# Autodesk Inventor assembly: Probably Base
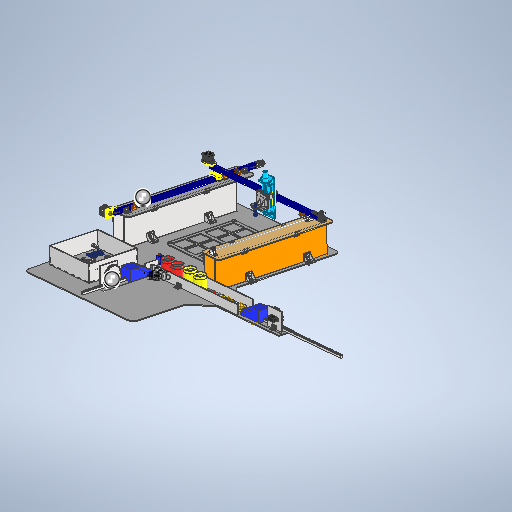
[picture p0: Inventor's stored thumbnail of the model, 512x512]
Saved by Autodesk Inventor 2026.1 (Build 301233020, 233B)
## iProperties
Created: 2026-10
Part Number: Probably Base
Document SubType Name: Assembly
Designer: hp
Author: hp
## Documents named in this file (64)
- C:\Users\hp\Documents\Inventor\DOM1_CartesianRobot\Probably Base.iam
- C:\Users\hp\Documents\Inventor\DOM1_CartesianRobot\StorageArea.ipt
- C:\Users\hp\Documents\Inventor\DOM1_CartesianRobot\BigBase.ipt
- C:\Users\hp\Documents\Inventor\DOM1_CartesianRobot\Side Wall Support.ipt
- C:\Users\hp\Documents\Inventor\DOM1_CartesianRobot\Belt Support.ipt
- C:\Users\hp\Documents\Inventor\DOM1_CartesianRobot\Assieme_guida_2020_nema.iam
- C:\Users\hp\Documents\Inventor\DOM1_CartesianRobot\Assieme_guida_2020_nema - Copy.iam
- C:\Users\hp\Documents\Inventor\DOM1_CartesianRobot\aluminum rod.ipt
- C:\Users\hp\Documents\Inventor\DOM1_CartesianRobot\color_sensor_holder.iam
- C:\Users\hp\Documents\Inventor\DOM1_CartesianRobot\IR_LM393_pin.ipt
- C:\Users\hp\Documents\Inventor\DOM1_CartesianRobot\reciever_wall.ipt
- C:\Users\hp\Documents\Inventor\DOM1_CartesianRobot\laser_assembly.iam
- C:\Users\hp\Documents\Inventor\DOM1_CartesianRobot\laser_detector.iam
- C:\Users\hp\Documents\Inventor\DOM1_CartesianRobot\pusher.iam
- C:\Users\hp\Documents\Inventor\DOM1_CartesianRobot\piatto.ipt
- C:\Users\hp\Documents\Inventor\DOM1_CartesianRobot\z axis screw.iam
- C:\Users\hp\Documents\Inventor\DOM1_CartesianRobot\z_Bearing_Housing_Assembly.iam
- C:\Users\hp\Documents\Inventor\DOM1_CartesianRobot\tool_mout_assembly.iam
- C:\Users\hp\Documents\Inventor\DOM1_CartesianRobot\Side Wall Support 2.ipt
- C:\Users\hp\Documents\Inventor\DOM1_CartesianRobot\filler.ipt
- C:\Users\hp\Documents\Inventor\DOM1_CartesianRobot\L-Bracket.ipt
- C:\Users\hp\Documents\Inventor\DOM1_CartesianRobot\Belt Support_v2.ipt
- C:\Users\hp\Documents\Inventor\DOM1_CartesianRobot\8mm_Railclamp.ipt
- C:\Users\hp\Documents\Inventor\DOM1_CartesianRobot\SC8UU Linear Rail Bearing v5.ipt
- C:\Users\hp\Documents\Inventor\Content Center Files\R2026\en-US\ISO 4017(1)\ISO 4017 - M10 x 25 - ISO.ipt
- C:\Users\hp\Documents\Inventor\Content Center Files\R2026\en-US\ISO 7041\ISO 7041 - M10 - ISO.ipt
- C:\Users\hp\Documents\Inventor\Content Center Files\R2026\en-US\ISO 4762(2)\ISO 4762 - M5 x 20ISO.ipt
- C:\Users\hp\Documents\Inventor\Content Center Files\R2026\en-US\ISO 7041\ISO 7041 - M5 - ISO.ipt
- C:\Users\hp\Documents\Inventor\DOM1_CartesianRobot\4040 Corner Bracket Right Angle L Shape.ipt
- C:\Users\hp\Documents\Inventor\Content Center Files\R2026\en-US\ISO 4762(2)\ISO 4762 - M6 x 20ISO.ipt
- C:\Users\hp\Documents\Inventor\Content Center Files\R2026\en-US\ISO 7041\ISO 7041 - M6 - ISO.ipt
- C:\Users\hp\Documents\Inventor\Content Center Files\R2026\en-US\JIS B 1111(2)\JIS B 1111 - M3x40(2).ipt
- C:\Users\hp\Documents\Inventor\DOM1_CartesianRobot\2020 M3.ipt
- C:\Users\hp\Documents\Inventor\Content Center Files\R2026\en-US\ISO 4017(1)\ISO 4017 - M4 x 35 - ISO.ipt
- C:\Users\hp\Documents\Inventor\DOM1_CartesianRobot\2020 M4 (1).ipt
- C:\Users\hp\Documents\Inventor\Content Center Files\R2026\en-US\ISO 4017(1)\ISO 4017 - M4 x 30 - ISO.ipt
- C:\Users\hp\Documents\Inventor\Content Center Files\R2026\en-US\ISO 4032(2)\ISO 4032 - M4 - ISO.ipt
- C:\Users\hp\Documents\Inventor\Content Center Files\R2026\en-US\ISO 4017(1)\ISO 4017 - M4 x 12 - ISO.ipt
- C:\Users\hp\Documents\Inventor\DOM1_CartesianRobot\feeder.iam
- C:\Users\hp\Documents\Inventor\DOM1_CartesianRobot\red_base.ipt
- C:\Users\hp\Documents\Inventor\DOM1_CartesianRobot\Feeder Side Wall.ipt
- C:\Users\hp\Documents\Inventor\Content Center Files\R2026\en-US\ISO 4017(1)\ISO 4017 - M4 x 8 - ISO.ipt
- C:\Users\hp\Documents\Inventor\Content Center Files\R2026\en-US\ISO 4017(1)\ISO 4017 - M5 x 20 - ISO.ipt
- C:\Users\hp\Documents\Inventor\Content Center Files\R2026\en-US\ISO 4032(2)\ISO 4032 - M5 - ISO.ipt
- C:\Users\hp\Documents\Inventor\DOM1_CartesianRobot\Side Wall Support_v1_B.ipt
- C:\Users\hp\Documents\Inventor\DOM1_CartesianRobot\Side Wall Support 2 (B).ipt
- C:\Users\hp\Documents\Inventor\Content Center Files\R2026\en-US\ISO 4017(1)\ISO 4017 - M8 x 25 - ISO.ipt
- C:\Users\hp\Documents\Inventor\Content Center Files\R2026\en-US\ISO 4032(2)\ISO 4032 - M8 - ISO.ipt
- C:\Users\hp\Documents\Inventor\Content Center Files\R2026\en-US\ISO 4017(1)\ISO 4017 - M8 x 16 - ISO.ipt
- C:\Users\hp\Documents\Inventor\Content Center Files\R2026\en-US\ISO 4017(1)\ISO 4017 - M8 x 20 - ISO.ipt
- C:\Users\hp\Documents\Inventor\Content Center Files\R2026\en-US\ISO 4035(2)\ISO 4035 - M4 - ISO.ipt
- C:\Users\hp\Documents\Inventor\DOM1_CartesianRobot\yellow_base.ipt
- C:\Users\hp\Documents\Inventor\DOM1_CartesianRobot\red_lid.ipt
- C:\Users\hp\Documents\Inventor\DOM1_CartesianRobot\yellow_lid.ipt
- C:\Users\hp\Documents\Inventor\DOM1_CartesianRobot\Color Sensor holder.ipt
- C:\Users\hp\Documents\Inventor\DOM1_CartesianRobot\color_sensor_holder_top.ipt
- C:\Users\hp\Documents\Inventor\Content Center Files\R2026\en-US\ISO 7045  H\ISO 7045 - M3 x 16_ - 4.8 - H - ISO.ipt
- C:\Users\hp\Documents\Inventor\Content Center Files\R2026\en-US\ISO 4032(2)\ISO 4032 - M3 - ISO.ipt
- C:\Users\hp\Documents\Inventor\Content Center Files\R2026\en-US\ISO 4014(2)\ISO 4014 - M5 x 25 - ISO.ipt
- C:\Users\hp\Documents\Inventor\DOM1_CartesianRobot\Control Box.iam
- C:\Users\hp\Documents\Inventor\DOM1_CartesianRobot\ESP-32.ipt
- C:\Users\hp\Documents\Inventor\DOM1_CartesianRobot\DRV8825_pin_heatsink.ipt
- C:\Users\hp\Documents\Inventor\DOM1_CartesianRobot\L298N Motor Driver.iam
- C:\Users\hp\Documents\Inventor\DOM1_CartesianRobot\Buck_XY3606.ipt
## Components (282 placed, 63 different names)
1. StorageArea:1
2. BigBase:1
3. Assieme_guida_2020_nema:1 [sub-assembly]
4. Side Wall Support:1
5. Side Wall Support_v1_B:1
6. Belt Support:1
7. Belt Support_v2:1
8. Assieme_guida_2020_nema - Copy:1 [sub-assembly]
9. color_sensor_holder:1 [sub-assembly] — Mate:649, Mate:650, Flush:61
10. IR_LM393_pin:1 — Mate:36, Mate:339, Mate:654
11. reciever_wall:1 — Mate:34, Flush:17, Mate:35, Flush:19
12. laser_assembly:1 [sub-assembly] — Mate:40, Mate:343
13. laser_detector:1 [sub-assembly] — Flush:19, Mate:41
14. piatto:1
15. piatto:2 — Mate:48, Slider:2, Mate:71, Mate:72, Mate:117, Mate:161
16. z_Bearing_Housing_Assembly:1 [sub-assembly]
17. tool_mout_assembly:1 [sub-assembly]
18. Side Wall Support 2:1
19. Side Wall Support 2 (B):1
20. filler:1 — Mate:79, Flush:30, Flush:31, Flush:33, Mate:170, Mate:172
21. L-Bracket:1
22. L-Bracket:2 — Mate:83, Mate:84, Mate:90, Mate:234, Mate:236, Mate:250, Mate:252
23. L-Bracket:3
24. L-Bracket:4
25. 8mm_Railclamp:1
26. 8mm_Railclamp:2 — Mate:92, Mate:93, Flush:37, Mate:434, Mate:436, Mate:442, Mate:444
27. aluminum rod:1 — Mate:94, Flush:38, Mate:95
28. SC8UU Linear Rail Bearing v5:1 — Mate:95, Angle:1, Flush:39, Mate:162, Mate:163, Mate:164, Mate:165
29. ISO 4017 M10 x 25:1 — Mate:96, Mate:97
30. ISO 7041 M10:1 — Mate:104, Mate:105
31. ISO 4017 M10 x 25:2 — Mate:98, Mate:99
32. ISO 4017 M10 x 25:3 — Mate:100, Mate:101
33. ISO 4017 M10 x 25:4 — Mate:102, Mate:103
34. ISO 7041 M10:2 — Mate:106, Mate:107
35. ISO 7041 M10:3 — Mate:108, Mate:109
36. ISO 7041 M10:4 — Mate:110, Mate:111
37. ISO 4762 M5 x 20:1 — Mate:114, Mate:115
38. ISO 7041 M5:1 — Mate:116, Mate:117
39. 4040 Corner Bracket Right Angle L Shape:1
40. 4040 Corner Bracket Right Angle L Shape:2
41. 4040 Corner Bracket Right Angle L Shape:3
42. 4040 Corner Bracket Right Angle L Shape:4 — Mate:124, Mate:125, Mate:127, Mate:478, Mate:510
43. 4040 Corner Bracket Right Angle L Shape:5 — Mate:135, Mate:137, Mate:480, Mate:512
44. 4040 Corner Bracket Right Angle L Shape:6 — Mate:134, Mate:136, Mate:179, Mate:464, Mate:488, Mate:520
45. 4040 Corner Bracket Right Angle L Shape:7 — Mate:130, Mate:133, Mate:484, Mate:516
46. 4040 Corner Bracket Right Angle L Shape:8
47. 4040 Corner Bracket Right Angle L Shape:9
48. 4040 Corner Bracket Right Angle L Shape:10
49. 4040 Corner Bracket Right Angle L Shape:11 — Mate:144, Mate:145, Mate:504, Mate:536
50. 4040 Corner Bracket Right Angle L Shape:12
51. 4040 Corner Bracket Right Angle L Shape:13
52. 4040 Corner Bracket Right Angle L Shape:14 — Mate:156, Mate:157, Mate:496, Mate:528
53. 4040 Corner Bracket Right Angle L Shape:15
54. 4040 Corner Bracket Right Angle L Shape:16 — Mate:151, Mate:152, Mate:459, Mate:461, Mate:492, Mate:524
55. ISO 4762 M6 x 20:1 — Mate:158, Mate:159
56. ISO 7041 M6:1 — Mate:160, Mate:161
57. JIS B 1111 M3x40:1 — Mate:162, Mate:163, Mate:168
58. JIS B 1111 M3x40:2 — Mate:164, Mate:165, Mate:169
59. 2020 M3:1 — Mate:166, Angle:2, Mate:168
60. 2020 M3:2 — Mate:167, Angle:3, Mate:169
61. ISO 4017 M4 x 35:1 — Mate:170, Mate:171, Mate:176
62. ISO 4017 M4 x 35:2 — Mate:172, Mate:173, Mate:177
63. 2020 M4 (1):1 — Mate:174, Angle:4, Mate:176
64. 2020 M4 (1):2 — Mate:175, Angle:5, Mate:177
65. L-Bracket:5
66. L-Bracket:6
67. L-Bracket:7
68. L-Bracket:8
69. L-Bracket:9
70. L-Bracket:10
71. L-Bracket:11
72. L-Bracket:12
73. ISO 4017 M4 x 30:1 — Mate:208, Mate:209
74. ISO 4032 M4:1 — Mate:216, Mate:217
75. ISO 4017 M4 x 30:2 — Mate:210, Mate:211
76. ISO 4017 M4 x 30:3 — Mate:212, Mate:213
77. ISO 4017 M4 x 30:4 — Mate:214, Mate:215
78. ISO 4032 M4:2 — Mate:218, Mate:219
79. ISO 4032 M4:3 — Mate:220, Mate:221
80. ISO 4032 M4:4 — Mate:222, Mate:223
81. ISO 4017 M4 x 12:1 — Mate:224, Mate:225
82. ISO 4032 M4:5 — Mate:240, Mate:241
83. ISO 4017 M4 x 12:2 — Mate:226, Mate:227
84. ISO 4017 M4 x 12:3 — Mate:228, Mate:229
85. ISO 4017 M4 x 12:4 — Mate:230, Mate:231
86. ISO 4017 M4 x 12:5 — Mate:232, Mate:233
87. ISO 4017 M4 x 12:6 — Mate:234, Mate:235
88. ISO 4017 M4 x 12:7 — Mate:236, Mate:237
89. ISO 4017 M4 x 12:8 — Mate:238, Mate:239
90. ISO 4032 M4:6 — Mate:242, Mate:243
91. ISO 4032 M4:7 — Mate:244, Mate:245
92. ISO 4032 M4:8 — Mate:246, Mate:247
93. ISO 4032 M4:9 — Mate:248, Mate:249
94. ISO 4032 M4:10 — Mate:250, Mate:251
95. ISO 4032 M4:11 — Mate:252, Mate:253
96. ISO 4032 M4:12 — Mate:254, Mate:255
97. ISO 4017 M4 x 12:9 — Mate:305, Mate:306
98. ISO 4032 M4:13 — Mate:321, Mate:322
99. ISO 4017 M4 x 12:10 — Mate:307, Mate:308
100. ISO 4017 M4 x 12:11 — Mate:309, Mate:310
101. ISO 4017 M4 x 12:12 — Mate:311, Mate:312
102. ISO 4017 M4 x 12:13 — Mate:313, Mate:314
103. ISO 4017 M4 x 12:14 — Mate:315, Mate:316
104. ISO 4017 M4 x 12:15 — Mate:317, Mate:318
105. ISO 4017 M4 x 12:16 — Mate:319, Mate:320
106. ISO 4032 M4:14 — Mate:323, Mate:324
107. ISO 4032 M4:15 — Mate:325, Mate:326
108. ISO 4032 M4:16 — Mate:327, Mate:328
109. ISO 4032 M4:17 — Mate:329, Mate:330
110. ISO 4032 M4:18 — Mate:331, Mate:332
111. ISO 4032 M4:19 — Mate:333, Mate:334
112. ISO 4032 M4:20 — Mate:335, Mate:336
113. feeder:1 [sub-assembly] — Flush:56, Flush:57, Flush:58, Mate:629, Mate:630, Mate:636, Mate:638
114. pusher:1 [sub-assembly] — Flush:45, Mate:337, Flush:48, Mate:611, Flush:59, Mate:617, Mate:619
115. red_base:1 — Mate:340
116. Feeder Side Wall:1 — Mate:361, Flush:54, Flush:55
117. Feeder Side Wall:2 — Mate:342, Flush:51, Flush:52, Mate:343, Mate:347
118. L-Bracket:13
119. L-Bracket:14
120. ISO 4017 M4 x 8:1 — Mate:357, Mate:358
121. ISO 4017 M4 x 8:2 — Mate:359, Mate:360
122. ISO 4017 M4 x 8:3 — Mate:362, Mate:363
123. ISO 4017 M4 x 8:4 — Mate:364, Mate:365
124. ISO 4017 M4 x 12:17 — Mate:366, Mate:367
125. ISO 4032 M4:21 — Mate:374, Mate:375
126. ISO 4017 M4 x 12:18 — Mate:368, Mate:369
127. ISO 4017 M4 x 12:19 — Mate:370, Mate:371
128. ISO 4017 M4 x 12:20 — Mate:372, Mate:373
129. ISO 4032 M4:22 — Mate:376, Mate:377
130. ISO 4032 M4:23 — Mate:378, Mate:379
131. ISO 4032 M4:24 — Mate:380, Mate:381
132. ISO 4017 M4 x 12:21 — Mate:382, Mate:383
133. ISO 4032 M4:25 — Mate:390, Mate:391
134. ISO 4017 M4 x 12:22 — Mate:384, Mate:385
135. ISO 4017 M4 x 12:23 — Mate:386, Mate:387
136. ISO 4017 M4 x 12:24 — Mate:388, Mate:389
137. ISO 4032 M4:26 — Mate:392, Mate:393
138. ISO 4032 M4:27 — Mate:394, Mate:395
139. ISO 4032 M4:28 — Mate:396, Mate:397
140. ISO 4017 M4 x 12:25 — Mate:398, Mate:399
141. ISO 4032 M4:29 — Mate:406, Mate:407
142. ISO 4017 M4 x 12:26 — Mate:400, Mate:401
143. ISO 4017 M4 x 12:27 — Mate:402, Mate:403
144. ISO 4017 M4 x 12:28 — Mate:404, Mate:405
145. ISO 4032 M4:30 — Mate:408, Mate:409
146. ISO 4032 M4:31 — Mate:410, Mate:411
147. ISO 4032 M4:32 — Mate:412, Mate:413
148. ISO 4017 M4 x 12:29 — Mate:414, Mate:415
149. ISO 4032 M4:33 — Mate:422, Mate:423
150. ISO 4017 M4 x 12:30 — Mate:416, Mate:417
151. ISO 4017 M4 x 12:31 — Mate:418, Mate:419
152. ISO 4017 M4 x 12:32 — Mate:420, Mate:421
153. ISO 4032 M4:34 — Mate:424, Mate:425
154. ISO 4032 M4:35 — Mate:426, Mate:427
155. ISO 4032 M4:36 — Mate:428, Mate:429
156. ISO 4017 M5 x 20:1 — Mate:430, Mate:431
157. ISO 4032 M5:1 — Mate:438, Mate:439
158. ISO 4017 M5 x 20:2 — Mate:432, Mate:433
159. ISO 4017 M5 x 20:3 — Mate:434, Mate:435
160. ISO 4017 M5 x 20:4 — Mate:436, Mate:437
161. ISO 4032 M5:2 — Mate:440, Mate:441
162. ISO 4032 M5:3 — Mate:442, Mate:443
163. ISO 4032 M5:4 — Mate:444, Mate:445
164. ISO 4017 M8 x 25:1 — Mate:446, Mate:447
165. ISO 4032 M8:1 — Mate:450, Mate:451
166. ISO 4017 M8 x 25:2 — Mate:448, Mate:449
167. ISO 4032 M8:2 — Mate:452, Mate:453
168. ISO 4017 M8 x 25:3 — Mate:454, Mate:455
169. ISO 4032 M8:3 — Mate:458, Mate:459
170. ISO 4017 M8 x 25:4 — Mate:456, Mate:457
171. ISO 4032 M8:4 — Mate:460, Mate:461
172. ISO 4017 M8 x 16:1 — Mate:462, Mate:463
173. ISO 4017 M8 x 16:2 — Mate:464, Mate:465
174. ISO 4017 M8 x 25:5 — Mate:466, Mate:467
175. ISO 4032 M8:5 — Mate:470, Mate:471
176. ISO 4017 M8 x 25:6 — Mate:468, Mate:469
177. ISO 4032 M8:6 — Mate:472, Mate:473
178. ISO 4017 M8 x 20:1 — Mate:474, Mate:475
179. ISO 4032 M8:7 — Mate:506, Mate:507
180. ISO 4017 M8 x 20:2 — Mate:476, Mate:477
181. ISO 4017 M8 x 20:3 — Mate:478, Mate:479
182. ISO 4017 M8 x 20:4 — Mate:480, Mate:481
183. ISO 4017 M8 x 20:5 — Mate:482, Mate:483
184. ISO 4017 M8 x 20:6 — Mate:484, Mate:485
185. ISO 4017 M8 x 20:7 — Mate:486, Mate:487
186. ISO 4017 M8 x 20:8 — Mate:488, Mate:489
187. ISO 4017 M8 x 20:9 — Mate:490, Mate:491
188. ISO 4017 M8 x 20:10 — Mate:492, Mate:493
189. ISO 4017 M8 x 20:11 — Mate:494, Mate:495
190. ISO 4017 M8 x 20:12 — Mate:496, Mate:497
191. ISO 4017 M8 x 20:13 — Mate:498, Mate:499
192. ISO 4017 M8 x 20:14 — Mate:500, Mate:501
193. ISO 4017 M8 x 20:15 — Mate:502, Mate:503
194. ISO 4017 M8 x 20:16 — Mate:504, Mate:505
195. ISO 4032 M8:8 — Mate:508, Mate:509
196. ISO 4032 M8:9 — Mate:510, Mate:511
197. ISO 4032 M8:10 — Mate:512, Mate:513
198. ISO 4032 M8:11 — Mate:514, Mate:515
199. ISO 4032 M8:12 — Mate:516, Mate:517
200. ISO 4032 M8:13 — Mate:518, Mate:519
201. ISO 4032 M8:14 — Mate:520, Mate:521
202. ISO 4032 M8:15 — Mate:522, Mate:523
203. ISO 4032 M8:16 — Mate:524, Mate:525
204. ISO 4032 M8:17 — Mate:526, Mate:527
205. ISO 4032 M8:18 — Mate:528, Mate:529
206. ISO 4032 M8:19 — Mate:530, Mate:531
207. ISO 4032 M8:20 — Mate:532, Mate:533
208. ISO 4032 M8:21 — Mate:534, Mate:535
209. ISO 4032 M8:22 — Mate:536, Mate:537
210. ISO 4017 M4 x 35:3 — Mate:538, Mate:539
211. ISO 4035 M4:1 — Mate:546, Mate:547
212. ISO 4017 M4 x 35:4 — Mate:540, Mate:541
213. ISO 4017 M4 x 35:5 — Mate:542, Mate:543
214. ISO 4017 M4 x 35:6 — Mate:544, Mate:545
215. ISO 4035 M4:2 — Mate:548, Mate:549
216. ISO 4035 M4:3 — Mate:550, Mate:551
217. ISO 4035 M4:4 — Mate:552, Mate:553
218. ISO 4017 M4 x 12:33 — Mate:554, Mate:555
219. ISO 4032 M4:37 — Mate:570, Mate:571
220. ISO 4017 M4 x 12:34 — Mate:556, Mate:557
221. ISO 4017 M4 x 12:35 — Mate:558, Mate:559
222. ISO 4017 M4 x 12:36 — Mate:560, Mate:561
223. ISO 4017 M4 x 12:37 — Mate:562, Mate:563
224. ISO 4017 M4 x 12:38 — Mate:564, Mate:565
225. ISO 4017 M4 x 12:39 — Mate:566, Mate:567
226. ISO 4017 M4 x 12:40 — Mate:568, Mate:569
227. ISO 4032 M4:38 — Mate:572, Mate:573
228. ISO 4032 M4:39 — Mate:574, Mate:575
229. ISO 4032 M4:40 — Mate:576, Mate:577
230. ISO 4032 M4:41 — Mate:578, Mate:579
231. ISO 4032 M4:42 — Mate:580, Mate:581
232. ISO 4032 M4:43 — Mate:582, Mate:583
233. ISO 4032 M4:44 — Mate:584, Mate:585
234. red_base:2 — Mate:586
235. yellow_base:1 — Mate:587
236. yellow_base:2 — Mate:588
237. red_lid:1 — Mate:589
238. red_lid:2 — Mate:591
239. yellow_lid:1 — Mate:590
240. yellow_lid:2 — Mate:592
241. ISO 4017 M4 x 12:41 — Mate:594, Mate:595
242. ISO 4032 M4:45 — Mate:602, Mate:603
243. ISO 4017 M4 x 12:42 — Mate:596, Mate:597
244. ISO 4017 M4 x 12:43 — Mate:598, Mate:599
245. ISO 4017 M4 x 12:44 — Mate:600, Mate:601
246. ISO 4032 M4:46 — Mate:604, Mate:605
247. ISO 4032 M4:47 — Mate:606, Mate:607
248. ISO 4032 M4:48 — Mate:608, Mate:609
249. L-Bracket:15
250. ISO 4017 M4 x 12:45 — Mate:612, Mate:613
251. ISO 4032 M4:49 — Mate:616, Mate:617
252. ISO 4017 M4 x 12:46 — Mate:614, Mate:615
253. ISO 4032 M4:50 — Mate:618, Mate:619
254. ISO 4017 M4 x 12:47 — Mate:620, Mate:621
255. ISO 4032 M4:51 — Mate:624, Mate:625
256. ISO 4017 M4 x 12:48 — Mate:622, Mate:623
257. ISO 4032 M4:52 — Mate:626, Mate:627
258. L-Bracket:16
259. ISO 4017 M4 x 12:49 — Mate:631, Mate:632
260. ISO 4032 M4:53 — Mate:635, Mate:636
261. ISO 4017 M4 x 12:50 — Mate:633, Mate:634
262. ISO 4032 M4:54 — Mate:637, Mate:638
263. ISO 4017 M4 x 12:51 — Mate:639, Mate:640
264. ISO 4032 M4:55 — Mate:643, Mate:644
265. ISO 4017 M4 x 12:52 — Mate:641, Mate:642
266. ISO 4032 M4:56 — Mate:645, Mate:646
267. Color Sensor holder:1
268. color_sensor_holder_top:1 — Mate:651, Mate:652
269. ISO 7045 H M3 x 16 - 4.8 - H:1 — Mate:653, Mate:654
270. ISO 4032 M3:1 — Mate:655, Mate:656
271. ISO 4014 M5 x 25:1 — Mate:658, Mate:659
272. ISO 4032 M5:5 — Mate:662, Mate:663
273. ISO 4014 M5 x 25:2 — Mate:660, Mate:661
274. ISO 4032 M5:6 — Mate:664, Mate:665
275. Control Box:1 [sub-assembly] — Mate:666, Flush:62, Mate:667, Mate:668, Mate:669, Mate:670, Mate:671, Mate:672
276. ESP-32:1 — Mate:668
277. ESP-32:2 — Mate:667
278. DRV8825_pin_heatsink:1
279. DRV8825_pin_heatsink:2
280. L298N Motor Driver:1 [sub-assembly] — Mate:669
281. Buck_XY3606:1 — Mate:672
282. z axis screw:1 [sub-assembly]
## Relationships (494: Mate 468, Flush 20, Angle 5, TranslationJoint 1)
- Mate:34: reciever_wall:1
- Flush:17: reciever_wall:1
- Mate:35: reciever_wall:1
- Mate:36: IR_LM393_pin:1
- Mate:40: laser_assembly:1
- Flush:19: reciever_wall:1 ↔ laser_detector:1
- Mate:41: laser_detector:1
- Mate:48: piatto:2
- Slider:2 [TranslationJoint]: piatto:2
- Mate:71: piatto:2
- Mate:72: piatto:2
- Mate:79: filler:1
- Flush:30: filler:1
- Flush:31: filler:1
- Mate:83: L-Bracket:2
- Mate:84: L-Bracket:2
- Mate:90: L-Bracket:2
- Flush:33: filler:1
- Mate:92: 8mm_Railclamp:2
- Mate:93: 8mm_Railclamp:2
- Flush:37: 8mm_Railclamp:2
- Mate:94: aluminum rod:1
- Flush:38: aluminum rod:1
- Mate:95: aluminum rod:1 ↔ SC8UU Linear Rail Bearing v5:1
- Angle:1: SC8UU Linear Rail Bearing v5:1
- Mate:96: ISO 4017 M10 x 25:1
- Mate:97: ISO 4017 M10 x 25:1
- Mate:98: ISO 4017 M10 x 25:2
- Mate:99: ISO 4017 M10 x 25:2
- Mate:100: ISO 4017 M10 x 25:3
- Mate:101: ISO 4017 M10 x 25:3
- Mate:102: ISO 4017 M10 x 25:4
- Mate:103: ISO 4017 M10 x 25:4
- Mate:104: ISO 7041 M10:1
- Mate:105: ISO 7041 M10:1
- Mate:106: ISO 7041 M10:2
- Mate:107: ISO 7041 M10:2
- Mate:108: ISO 7041 M10:3
- Mate:109: ISO 7041 M10:3
- Mate:110: ISO 7041 M10:4
- Mate:111: ISO 7041 M10:4
- Mate:114: ISO 4762 M5 x 20:1
- Mate:115: ISO 4762 M5 x 20:1
- Mate:116: ISO 7041 M5:1
- Mate:117: piatto:2 ↔ ISO 7041 M5:1
- Mate:124: 4040 Corner Bracket Right Angle L Shape:4
- Mate:125: 4040 Corner Bracket Right Angle L Shape:4
- Mate:127: 4040 Corner Bracket Right Angle L Shape:4
- Mate:130: 4040 Corner Bracket Right Angle L Shape:7
- Mate:133: 4040 Corner Bracket Right Angle L Shape:7
- Mate:134: 4040 Corner Bracket Right Angle L Shape:6
- Mate:135: 4040 Corner Bracket Right Angle L Shape:5
- Mate:136: 4040 Corner Bracket Right Angle L Shape:6
- Mate:137: 4040 Corner Bracket Right Angle L Shape:5
- Mate:144: 4040 Corner Bracket Right Angle L Shape:11
- Mate:145: 4040 Corner Bracket Right Angle L Shape:11
- Mate:151: 4040 Corner Bracket Right Angle L Shape:16
- Mate:152: 4040 Corner Bracket Right Angle L Shape:16
- Mate:156: 4040 Corner Bracket Right Angle L Shape:14
- Mate:157: 4040 Corner Bracket Right Angle L Shape:14
- Mate:158: ISO 4762 M6 x 20:1
- Mate:159: ISO 4762 M6 x 20:1
- Mate:160: ISO 7041 M6:1
- Mate:161: piatto:2 ↔ ISO 7041 M6:1
- Flush:39: SC8UU Linear Rail Bearing v5:1
- Mate:162: SC8UU Linear Rail Bearing v5:1 ↔ JIS B 1111 M3x40:1
- Mate:163: SC8UU Linear Rail Bearing v5:1 ↔ JIS B 1111 M3x40:1
- Mate:164: SC8UU Linear Rail Bearing v5:1 ↔ JIS B 1111 M3x40:2
- Mate:165: SC8UU Linear Rail Bearing v5:1 ↔ JIS B 1111 M3x40:2
- Mate:166: 2020 M3:1
- Mate:167: 2020 M3:2
- Angle:2: 2020 M3:1
- Angle:3: 2020 M3:2
- Mate:168: JIS B 1111 M3x40:1 ↔ 2020 M3:1
- Mate:169: JIS B 1111 M3x40:2 ↔ 2020 M3:2
- Mate:170: filler:1 ↔ ISO 4017 M4 x 35:1
- Mate:171: ISO 4017 M4 x 35:1
- Mate:172: filler:1 ↔ ISO 4017 M4 x 35:2
- Mate:173: ISO 4017 M4 x 35:2
- Mate:174: 2020 M4 (1):1
- Mate:175: 2020 M4 (1):2
- Angle:4: 2020 M4 (1):1
- Angle:5: 2020 M4 (1):2
- Mate:176: ISO 4017 M4 x 35:1 ↔ 2020 M4 (1):1
- Mate:177: ISO 4017 M4 x 35:2 ↔ 2020 M4 (1):2
- Mate:179: 4040 Corner Bracket Right Angle L Shape:6
- Mate:208: ISO 4017 M4 x 30:1
- Mate:209: ISO 4017 M4 x 30:1
- Mate:210: ISO 4017 M4 x 30:2
- Mate:211: ISO 4017 M4 x 30:2
- Mate:212: ISO 4017 M4 x 30:3
- Mate:213: ISO 4017 M4 x 30:3
- Mate:214: ISO 4017 M4 x 30:4
- Mate:215: ISO 4017 M4 x 30:4
- Mate:216: ISO 4032 M4:1
- Mate:217: ISO 4032 M4:1
- Mate:218: ISO 4032 M4:2
- Mate:219: ISO 4032 M4:2
- Mate:220: ISO 4032 M4:3
- Mate:221: ISO 4032 M4:3
- Mate:222: ISO 4032 M4:4
- Mate:223: ISO 4032 M4:4
- Mate:224: ISO 4017 M4 x 12:1
- Mate:225: ISO 4017 M4 x 12:1
- Mate:226: ISO 4017 M4 x 12:2
- Mate:227: ISO 4017 M4 x 12:2
- Mate:228: ISO 4017 M4 x 12:3
- Mate:229: ISO 4017 M4 x 12:3
- Mate:230: ISO 4017 M4 x 12:4
- Mate:231: ISO 4017 M4 x 12:4
- Mate:232: ISO 4017 M4 x 12:5
- Mate:233: ISO 4017 M4 x 12:5
- Mate:234: L-Bracket:2 ↔ ISO 4017 M4 x 12:6
- Mate:235: ISO 4017 M4 x 12:6
- Mate:236: L-Bracket:2 ↔ ISO 4017 M4 x 12:7
- Mate:237: ISO 4017 M4 x 12:7
- Mate:238: ISO 4017 M4 x 12:8
- Mate:239: ISO 4017 M4 x 12:8
- Mate:240: ISO 4032 M4:5
- Mate:241: ISO 4032 M4:5
- Mate:242: ISO 4032 M4:6
- Mate:243: ISO 4032 M4:6
- Mate:244: ISO 4032 M4:7
- Mate:245: ISO 4032 M4:7
- Mate:246: ISO 4032 M4:8
- Mate:247: ISO 4032 M4:8
- Mate:248: ISO 4032 M4:9
- Mate:249: ISO 4032 M4:9
- Mate:250: L-Bracket:2 ↔ ISO 4032 M4:10
- Mate:251: ISO 4032 M4:10
- Mate:252: L-Bracket:2 ↔ ISO 4032 M4:11
- Mate:253: ISO 4032 M4:11
- Mate:254: ISO 4032 M4:12
- Mate:255: ISO 4032 M4:12
- Mate:305: ISO 4017 M4 x 12:9
- Mate:306: ISO 4017 M4 x 12:9
- Mate:307: ISO 4017 M4 x 12:10
- Mate:308: ISO 4017 M4 x 12:10
- Mate:309: ISO 4017 M4 x 12:11
- Mate:310: ISO 4017 M4 x 12:11
- Mate:311: ISO 4017 M4 x 12:12
- Mate:312: ISO 4017 M4 x 12:12
- Mate:313: ISO 4017 M4 x 12:13
- Mate:314: ISO 4017 M4 x 12:13
- Mate:315: ISO 4017 M4 x 12:14
- Mate:316: ISO 4017 M4 x 12:14
- Mate:317: ISO 4017 M4 x 12:15
- Mate:318: ISO 4017 M4 x 12:15
- Mate:319: ISO 4017 M4 x 12:16
- Mate:320: ISO 4017 M4 x 12:16
- Mate:321: ISO 4032 M4:13
- Mate:322: ISO 4032 M4:13
- Mate:323: ISO 4032 M4:14
- Mate:324: ISO 4032 M4:14
- Mate:325: ISO 4032 M4:15
- Mate:326: ISO 4032 M4:15
- Mate:327: ISO 4032 M4:16
- Mate:328: ISO 4032 M4:16
- Mate:329: ISO 4032 M4:17
- Mate:330: ISO 4032 M4:17
- Mate:331: ISO 4032 M4:18
- Mate:332: ISO 4032 M4:18
- Mate:333: ISO 4032 M4:19
- Mate:334: ISO 4032 M4:19
- Mate:335: ISO 4032 M4:20
- Mate:336: ISO 4032 M4:20
- Flush:45: pusher:1
- Mate:337: pusher:1
- Mate:339: IR_LM393_pin:1
- Mate:340: red_base:1
- Flush:48: pusher:1
- Mate:342: Feeder Side Wall:2
- Flush:51: Feeder Side Wall:2
- Flush:52: Feeder Side Wall:2
- Mate:343: laser_assembly:1 ↔ Feeder Side Wall:2
- Mate:347: Feeder Side Wall:2
- Mate:357: ISO 4017 M4 x 8:1
- Mate:358: ISO 4017 M4 x 8:1
- Mate:359: ISO 4017 M4 x 8:2
- Mate:360: ISO 4017 M4 x 8:2
- Mate:361: Feeder Side Wall:1
- Flush:54: Feeder Side Wall:1
- Flush:55: Feeder Side Wall:1
- Mate:362: ISO 4017 M4 x 8:3
- Mate:363: ISO 4017 M4 x 8:3
- Mate:364: ISO 4017 M4 x 8:4
- Mate:365: ISO 4017 M4 x 8:4
- Mate:366: ISO 4017 M4 x 12:17
- Mate:367: ISO 4017 M4 x 12:17
- Mate:368: ISO 4017 M4 x 12:18
- Mate:369: ISO 4017 M4 x 12:18
- Mate:370: ISO 4017 M4 x 12:19
- Mate:371: ISO 4017 M4 x 12:19
- Mate:372: ISO 4017 M4 x 12:20
- Mate:373: ISO 4017 M4 x 12:20
- Mate:374: ISO 4032 M4:21
- Mate:375: ISO 4032 M4:21
- Mate:376: ISO 4032 M4:22
- Mate:377: ISO 4032 M4:22
- Mate:378: ISO 4032 M4:23
- Mate:379: ISO 4032 M4:23
- Mate:380: ISO 4032 M4:24
- Mate:381: ISO 4032 M4:24
- Mate:382: ISO 4017 M4 x 12:21
- Mate:383: ISO 4017 M4 x 12:21
- Mate:384: ISO 4017 M4 x 12:22
- Mate:385: ISO 4017 M4 x 12:22
- Mate:386: ISO 4017 M4 x 12:23
- Mate:387: ISO 4017 M4 x 12:23
- Mate:388: ISO 4017 M4 x 12:24
- Mate:389: ISO 4017 M4 x 12:24
- Mate:390: ISO 4032 M4:25
- Mate:391: ISO 4032 M4:25
- Mate:392: ISO 4032 M4:26
- Mate:393: ISO 4032 M4:26
- Mate:394: ISO 4032 M4:27
- Mate:395: ISO 4032 M4:27
- Mate:396: ISO 4032 M4:28
- Mate:397: ISO 4032 M4:28
- Mate:398: ISO 4017 M4 x 12:25
- Mate:399: ISO 4017 M4 x 12:25
- Mate:400: ISO 4017 M4 x 12:26
- Mate:401: ISO 4017 M4 x 12:26
- Mate:402: ISO 4017 M4 x 12:27
- Mate:403: ISO 4017 M4 x 12:27
- Mate:404: ISO 4017 M4 x 12:28
- Mate:405: ISO 4017 M4 x 12:28
- Mate:406: ISO 4032 M4:29
- Mate:407: ISO 4032 M4:29
- Mate:408: ISO 4032 M4:30
- Mate:409: ISO 4032 M4:30
- Mate:410: ISO 4032 M4:31
- Mate:411: ISO 4032 M4:31
- Mate:412: ISO 4032 M4:32
- Mate:413: ISO 4032 M4:32
- Mate:414: ISO 4017 M4 x 12:29
- Mate:415: ISO 4017 M4 x 12:29
- Mate:416: ISO 4017 M4 x 12:30
- Mate:417: ISO 4017 M4 x 12:30
- Mate:418: ISO 4017 M4 x 12:31
- Mate:419: ISO 4017 M4 x 12:31
- Mate:420: ISO 4017 M4 x 12:32
- Mate:421: ISO 4017 M4 x 12:32
- Mate:422: ISO 4032 M4:33
- Mate:423: ISO 4032 M4:33
- Mate:424: ISO 4032 M4:34
- Mate:425: ISO 4032 M4:34
- Mate:426: ISO 4032 M4:35
- Mate:427: ISO 4032 M4:35
- Mate:428: ISO 4032 M4:36
- Mate:429: ISO 4032 M4:36
- Mate:430: ISO 4017 M5 x 20:1
- Mate:431: ISO 4017 M5 x 20:1
- Mate:432: ISO 4017 M5 x 20:2
- Mate:433: ISO 4017 M5 x 20:2
- Mate:434: 8mm_Railclamp:2 ↔ ISO 4017 M5 x 20:3
- Mate:435: ISO 4017 M5 x 20:3
- Mate:436: 8mm_Railclamp:2 ↔ ISO 4017 M5 x 20:4
- Mate:437: ISO 4017 M5 x 20:4
- Mate:438: ISO 4032 M5:1
- Mate:439: ISO 4032 M5:1
- Mate:440: ISO 4032 M5:2
- Mate:441: ISO 4032 M5:2
- Mate:442: 8mm_Railclamp:2 ↔ ISO 4032 M5:3
- Mate:443: ISO 4032 M5:3
- Mate:444: 8mm_Railclamp:2 ↔ ISO 4032 M5:4
- Mate:445: ISO 4032 M5:4
- Mate:446: ISO 4017 M8 x 25:1
- Mate:447: ISO 4017 M8 x 25:1
- Mate:448: ISO 4017 M8 x 25:2
- Mate:449: ISO 4017 M8 x 25:2
- Mate:450: ISO 4032 M8:1
- Mate:451: ISO 4032 M8:1
- Mate:452: ISO 4032 M8:2
- Mate:453: ISO 4032 M8:2
- Mate:454: ISO 4017 M8 x 25:3
- Mate:455: ISO 4017 M8 x 25:3
- Mate:456: ISO 4017 M8 x 25:4
- Mate:457: ISO 4017 M8 x 25:4
- Mate:458: ISO 4032 M8:3
- Mate:459: 4040 Corner Bracket Right Angle L Shape:16 ↔ ISO 4032 M8:3
- Mate:460: ISO 4032 M8:4
- Mate:461: 4040 Corner Bracket Right Angle L Shape:16 ↔ ISO 4032 M8:4
- Mate:462: ISO 4017 M8 x 16:1
- Mate:463: ISO 4017 M8 x 16:1
- Mate:464: 4040 Corner Bracket Right Angle L Shape:6 ↔ ISO 4017 M8 x 16:2
- Mate:465: ISO 4017 M8 x 16:2
- Mate:466: ISO 4017 M8 x 25:5
- Mate:467: ISO 4017 M8 x 25:5
- Mate:468: ISO 4017 M8 x 25:6
- Mate:469: ISO 4017 M8 x 25:6
- Mate:470: ISO 4032 M8:5
- Mate:471: ISO 4032 M8:5
- Mate:472: ISO 4032 M8:6
- Mate:473: ISO 4032 M8:6
- Mate:474: ISO 4017 M8 x 20:1
- Mate:475: ISO 4017 M8 x 20:1
- Mate:476: ISO 4017 M8 x 20:2
- Mate:477: ISO 4017 M8 x 20:2
- Mate:478: 4040 Corner Bracket Right Angle L Shape:4 ↔ ISO 4017 M8 x 20:3
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## Named parameters: d288_d286 = 0, d289_d286 = 0, d298_d289_d286 = 0, d299_d288_d286 = 0, d308_d289_d286 = 0, d309_d288_d286 = 0
